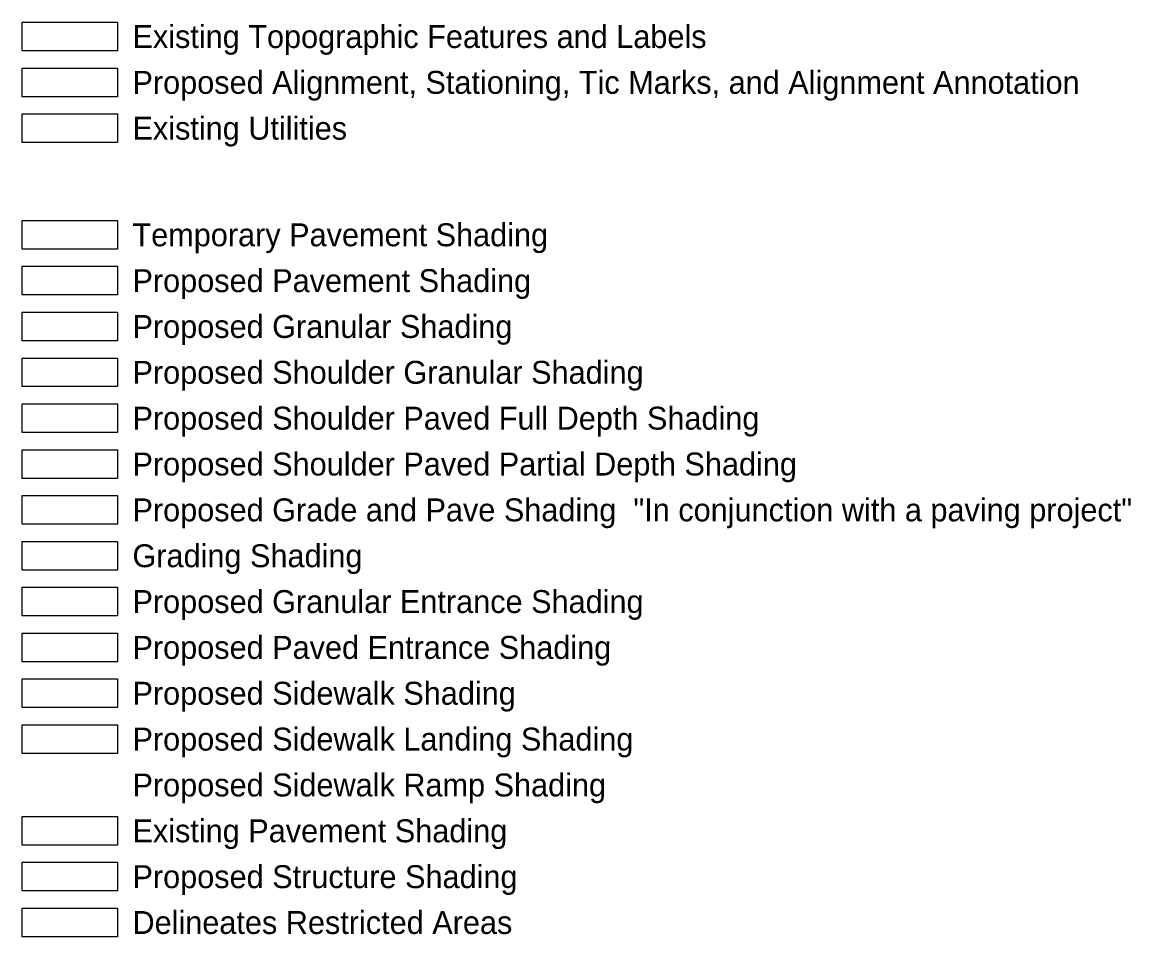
# Model space of a CAD drawing. Extents: x 20499216 to 20505321, y 7953487 to 7960535.
# Drawn here: x 20499215.9 to 20499276.3, y 7955648.6 to 7955698.5 of the extents above; entities that cross this region are included whole.
import ezdxf

# ---------------------------------------------------------------- set-up
doc = ezdxf.new("R2010")
doc.units = 0
for name, color, linetype in [('NamedBoundary', 7, 'Continuous'), ('SurPropertyCells', 7, 'Continuous'), ('SurUtilityCells', 7, 'Continuous'), ('SurUtilityPoleCell', 7, 'Continuous'), ('SurUtilityStructureCell', 7, 'Continuous'), ('Text', 7, 'Continuous'), ('UtilitiesAboveGround', 7, 'Continuous'), ('UtilitiesBelowGround', 7, 'Continuous')]:
    doc.layers.add(name, color=color, linetype=linetype)

msp = doc.modelspace()

# ---------------------------------------------------------------- linework, layer by layer
at = {"layer": 'NamedBoundary'}
for points in [[(20499215.863, 7955685.184), (20499221.071, 7955685.184), (20499221.071, 7955683.622), (20499215.863, 7955683.622)], [(20499215.863, 7955682.684), (20499221.071, 7955682.684), (20499221.071, 7955681.122), (20499215.863, 7955681.122)], [(20499215.863, 7955680.184), (20499221.071, 7955680.184), (20499221.071, 7955678.622), (20499215.863, 7955678.622)], [(20499215.863, 7955677.684), (20499221.071, 7955677.684), (20499221.071, 7955676.122), (20499215.863, 7955676.122)], [(20499215.863, 7955675.184), (20499221.071, 7955675.184), (20499221.071, 7955673.622), (20499215.863, 7955673.622)], [(20499215.863, 7955667.684), (20499221.071, 7955667.684), (20499221.071, 7955666.122), (20499215.863, 7955666.122)], [(20499215.863, 7955665.184), (20499221.071, 7955665.184), (20499221.071, 7955663.622), (20499215.863, 7955663.622)], [(20499215.863, 7955655.184), (20499221.071, 7955655.184), (20499221.071, 7955653.622), (20499215.863, 7955653.622)], [(20499215.863, 7955652.684), (20499221.071, 7955652.684), (20499221.071, 7955651.122), (20499215.863, 7955651.122)], [(20499215.863, 7955650.184), (20499221.071, 7955650.184), (20499221.071, 7955648.622), (20499215.863, 7955648.622)]]:
    msp.add_lwpolyline(points, close=True, dxfattribs=at)
at = {"layer": 'SurPropertyCells'}
msp.add_lwpolyline([(20499215.863, 7955698.497), (20499221.071, 7955698.497), (20499221.071, 7955696.934), (20499215.863, 7955696.934)], close=True, dxfattribs=at)
at = {"layer": 'SurUtilityCells'}
for points in [[(20499215.863, 7955672.684), (20499221.071, 7955672.684), (20499221.071, 7955671.122), (20499215.863, 7955671.122)], [(20499215.863, 7955662.684), (20499221.071, 7955662.684), (20499221.071, 7955661.122), (20499215.863, 7955661.122)], [(20499215.863, 7955660.184), (20499221.071, 7955660.184), (20499221.071, 7955658.622), (20499215.863, 7955658.622)]]:
    msp.add_lwpolyline(points, close=True, dxfattribs=at)
at = {"layer": 'SurUtilityPoleCell'}
msp.add_lwpolyline([(20499215.863, 7955670.184), (20499221.071, 7955670.184), (20499221.071, 7955668.622), (20499215.863, 7955668.622)], close=True, dxfattribs=at)
at = {"layer": 'SurUtilityStructureCell'}
msp.add_lwpolyline([(20499215.863, 7955693.497), (20499221.071, 7955693.497), (20499221.071, 7955691.934), (20499215.863, 7955691.934)], close=True, dxfattribs=at)
at = {"layer": 'Text'}
msp.add_lwpolyline([(20499215.863, 7955687.684), (20499221.071, 7955687.684), (20499221.071, 7955686.122), (20499215.863, 7955686.122)], close=True, dxfattribs=at)
at = {"layer": 'UtilitiesAboveGround'}
msp.add_lwpolyline([(20499215.863, 7955695.997), (20499221.071, 7955695.997), (20499221.071, 7955694.434), (20499215.863, 7955694.434)], close=True, dxfattribs=at)

# ---------------------------------------------------------------- texts
at = {"layer": 'UtilitiesBelowGround'}
for s, p in [('Existing Topographic Features and Labels', (20499221.879, 7955697.089)), ('Proposed Alignment, Stationing, Tic Marks, and Alignment Annotation ', (20499221.879, 7955694.589)), ('Existing Utilities ', (20499221.879, 7955692.089)), ('Temporary Pavement Shading', (20499221.879, 7955686.277)), ('Proposed Pavement Shading', (20499221.879, 7955683.777)), ('Proposed Granular Shading', (20499221.879, 7955681.277)), ('Proposed Shoulder Granular Shading', (20499221.879, 7955678.777)), ('Proposed Shoulder Paved Full Depth Shading', (20499221.879, 7955676.277)), ('Proposed Shoulder Paved Partial Depth Shading', (20499221.879, 7955673.777)), ('Proposed Grade and Pave Shading  "In conjunction with a paving project"', (20499221.879, 7955671.277)), ('Grading Shading', (20499221.879, 7955668.777)), ('Proposed Granular Entrance Shading', (20499221.879, 7955666.277)), ('Proposed Paved Entrance Shading', (20499221.879, 7955663.777)), ('Proposed Sidewalk Shading', (20499221.879, 7955661.277)), ('Proposed Sidewalk Landing Shading', (20499221.879, 7955658.777)), ('Proposed Sidewalk Ramp Shading', (20499221.879, 7955656.277)), ('Existing Pavement Shading', (20499221.879, 7955653.777)), ('Proposed Structure Shading', (20499221.879, 7955651.277)), ('Delineates Restricted Areas', (20499221.879, 7955648.777))]:
    msp.add_text(s, height=1.25, dxfattribs=at).set_placement(p)

doc.saveas('drawing.dxf')
